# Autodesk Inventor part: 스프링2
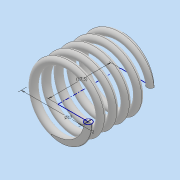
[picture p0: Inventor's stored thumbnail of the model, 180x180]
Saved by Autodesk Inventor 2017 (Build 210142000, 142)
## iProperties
Part Number: 스프링2
Material: 일반
Document SubType Name: Modeling
Designer: MRC
Density: 1 g/cm^3
Appearance: 기본값
Mass: 0.819704 g
Surface Area: 16.7052 cm^2
Volume: 0.819704 cm^3
Author: MRC
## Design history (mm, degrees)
sketch "스케치1"
  geometry: L1 (0, 0)-(0, 17.5); L2 (0, 0)-(8.5, 0); L3 (0, 17.5)-(7.5, 17.5); C1 r 1 at (8.5, 0)
  constraints: 6 end point, 2 horizontal, 1 centre point, 1 coincident, 1 vertical
  dimensions: "d0" = 17.5 distance of L1.start L1.end (derived); "d1" = 2 diameter of C1; "d2" = 17 diameter of L2.end L1
feature "코일1" sketch "스케치1" pitch "d3" = 10; turns "d5" = 5; dims "d4" = 17.5 (= d0), "d6" = 0, angle "d7" = 90 deg, angle "d8" = 90 deg, "d9" = 0, "d10" = 0
sketch "스케치2"
  geometry: L1 (17.5, 18.5)-(0, 18.5); L2 (0, 18.5)-(0, -18.5); L3 (0, -18.5)-(17.5, -18.5); L4 (17.5, -18.5)-(17.5, 18.5); 2 further points
  constraints: 8 end point, 2 parallel, 1 coincident, 1 horizontal, 1 midpoint, 1 perpendicular
  dimensions: "d11" = 37 distance of L3.end L1.start; "d12" = 17.5 distance of L2.end L3.end (= d0)
extrude "돌출1" sketch "스케치2" stored distance "d13" = 0; taper "d14" = 0 deg
node "솔리드1"
